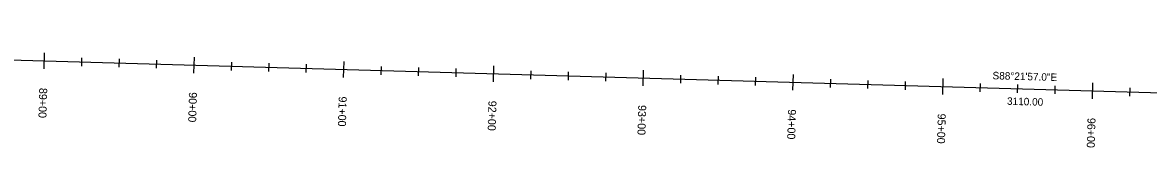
# Model space of a CAD drawing. Extents: x 2301963 to 2307911, y 760768 to 761974.
# Drawn here: x 2305677 to 2306429, y 760810 to 760898 of the extents above; entities that cross this region are included whole.
import ezdxf

# ---------------------------------------------------------------- set-up
doc = ezdxf.new("R2010")
doc.units = 0
for name, color, linetype in [('Default', 7, 'Continuous'), ('Draft_Bearing Label', 7, 'Continuous'), ('Draft_Station Labels Major', 7, 'Continuous'), ('Draft_Station Ticks Major', 7, 'Continuous'), ('Draft_Station Ticks Minor', 7, 'Continuous'), ('Geom_Secondary', 7, 'Continuous')]:
    doc.layers.add(name, color=color, linetype=linetype)

msp = doc.modelspace()

# ---------------------------------------------------------------- linework, layer by layer
at = {"layer": 'Default'}
msp.add_line((2304792.58, 760898.19), (2307901.31, 760809.5), dxfattribs=at)
at = {"layer": 'Draft_Station Ticks Major'}
for p, q in [((2305691.88, 760877.88), (2305691.58, 760867.26)), ((2305791.84, 760875.02), (2305791.54, 760864.41)), ((2305891.8, 760872.17), (2305891.5, 760861.56)), ((2305991.76, 760869.32), (2305991.45, 760858.71)), ((2306091.72, 760866.47), (2306091.41, 760855.85)), ((2306191.68, 760863.62), (2306191.37, 760853)), ((2306291.64, 760860.77), (2306291.33, 760850.15)), ((2306391.59, 760857.91), (2306391.29, 760847.3))]:
    msp.add_line(p, q, dxfattribs=at)
at = {"layer": 'Draft_Station Ticks Minor'}
for p, q in [((2305716.8, 760874.58), (2305716.64, 760869.07)), ((2305741.79, 760873.87), (2305741.63, 760868.35)), ((2305766.78, 760873.16), (2305766.62, 760867.64)), ((2305816.76, 760871.73), (2305816.6, 760866.21)), ((2305841.74, 760871.02), (2305841.59, 760865.5)), ((2305866.73, 760870.31), (2305866.58, 760864.79)), ((2305916.71, 760868.88), (2305916.56, 760863.36)), ((2305941.7, 760868.17), (2305941.55, 760862.65)), ((2305966.69, 760867.45), (2305966.54, 760861.94)), ((2306016.67, 760866.03), (2306016.52, 760860.51)), ((2306041.66, 760865.32), (2306041.51, 760859.8)), ((2306066.65, 760864.6), (2306066.5, 760859.09)), ((2306116.63, 760863.18), (2306116.48, 760857.66)), ((2306141.62, 760862.46), (2306141.47, 760856.95)), ((2306166.61, 760861.75), (2306166.46, 760856.23)), ((2306216.59, 760860.33), (2306216.43, 760854.81)), ((2306241.58, 760859.61), (2306241.42, 760854.09)), ((2306266.57, 760858.9), (2306266.41, 760853.38)), ((2306316.55, 760857.47), (2306316.39, 760851.96)), ((2306341.54, 760856.76), (2306341.38, 760851.24)), ((2306366.53, 760856.05), (2306366.37, 760850.53)), ((2306416.51, 760854.62), (2306416.35, 760849.1))]:
    msp.add_line(p, q, dxfattribs=at)
at = {"layer": 'Geom_Secondary'}
msp.add_line((2304792.58, 760898.19), (2307901.31, 760809.5), dxfattribs=at)

# ---------------------------------------------------------------- texts
at = {"layer": 'Draft_Bearing Label'}
for s, p in [('S88°21\'57.0"E', (2306324.78, 760860.36)), ('3110.00', (2306334.45, 760843.32))]:
    msp.add_text(s, height=5, rotation=358.36584, dxfattribs=at).set_placement(p)
at = {"layer": 'Draft_Station Labels Major'}
for s, p in [('89+00', (2305688.54, 760854.62)), ('90+00', (2305788.5, 760851.77)), ('91+00', (2305888.46, 760848.92)), ('92+00', (2305988.42, 760846.07)), ('93+00', (2306088.38, 760843.21)), ('94+00', (2306188.34, 760840.36)), ('95+00', (2306288.3, 760837.51)), ('96+00', (2306388.26, 760834.66))]:
    msp.add_text(s, height=5.34, rotation=268.36584, dxfattribs=at).set_placement(p)

doc.saveas('drawing.dxf')
